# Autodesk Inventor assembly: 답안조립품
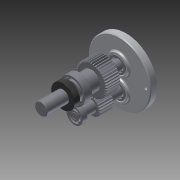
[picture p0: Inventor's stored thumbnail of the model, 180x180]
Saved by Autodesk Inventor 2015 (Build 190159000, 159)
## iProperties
Created: 2016-02
Part Number: 답안조립품
Document SubType Name: Assembly
Designer: Administrator
Author: Administrator
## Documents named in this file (9)
- C:\Users\Administrator\Desktop\460209V1006\답안조립품.iam
- C:\Users\Administrator\Desktop\460209V1006\본체.ipt
- C:\Users\Administrator\Desktop\460209V1006\커버.ipt
- C:\Users\Administrator\Desktop\460209V1006\오일실 17 32 8.ipt
- C:\Users\Administrator\Desktop\460209V1006\오일실 8 22 7.ipt
- C:\Users\Administrator\Desktop\460209V1006\베어링 608.ipt
- C:\Users\Administrator\Desktop\460209V1006\메인축.ipt
- C:\Users\Administrator\Desktop\460209V1006\서브축.ipt
- C:\Users\Administrator\Desktop\460209V1006\베어링 6003.ipt
